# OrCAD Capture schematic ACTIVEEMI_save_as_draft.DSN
size Custom
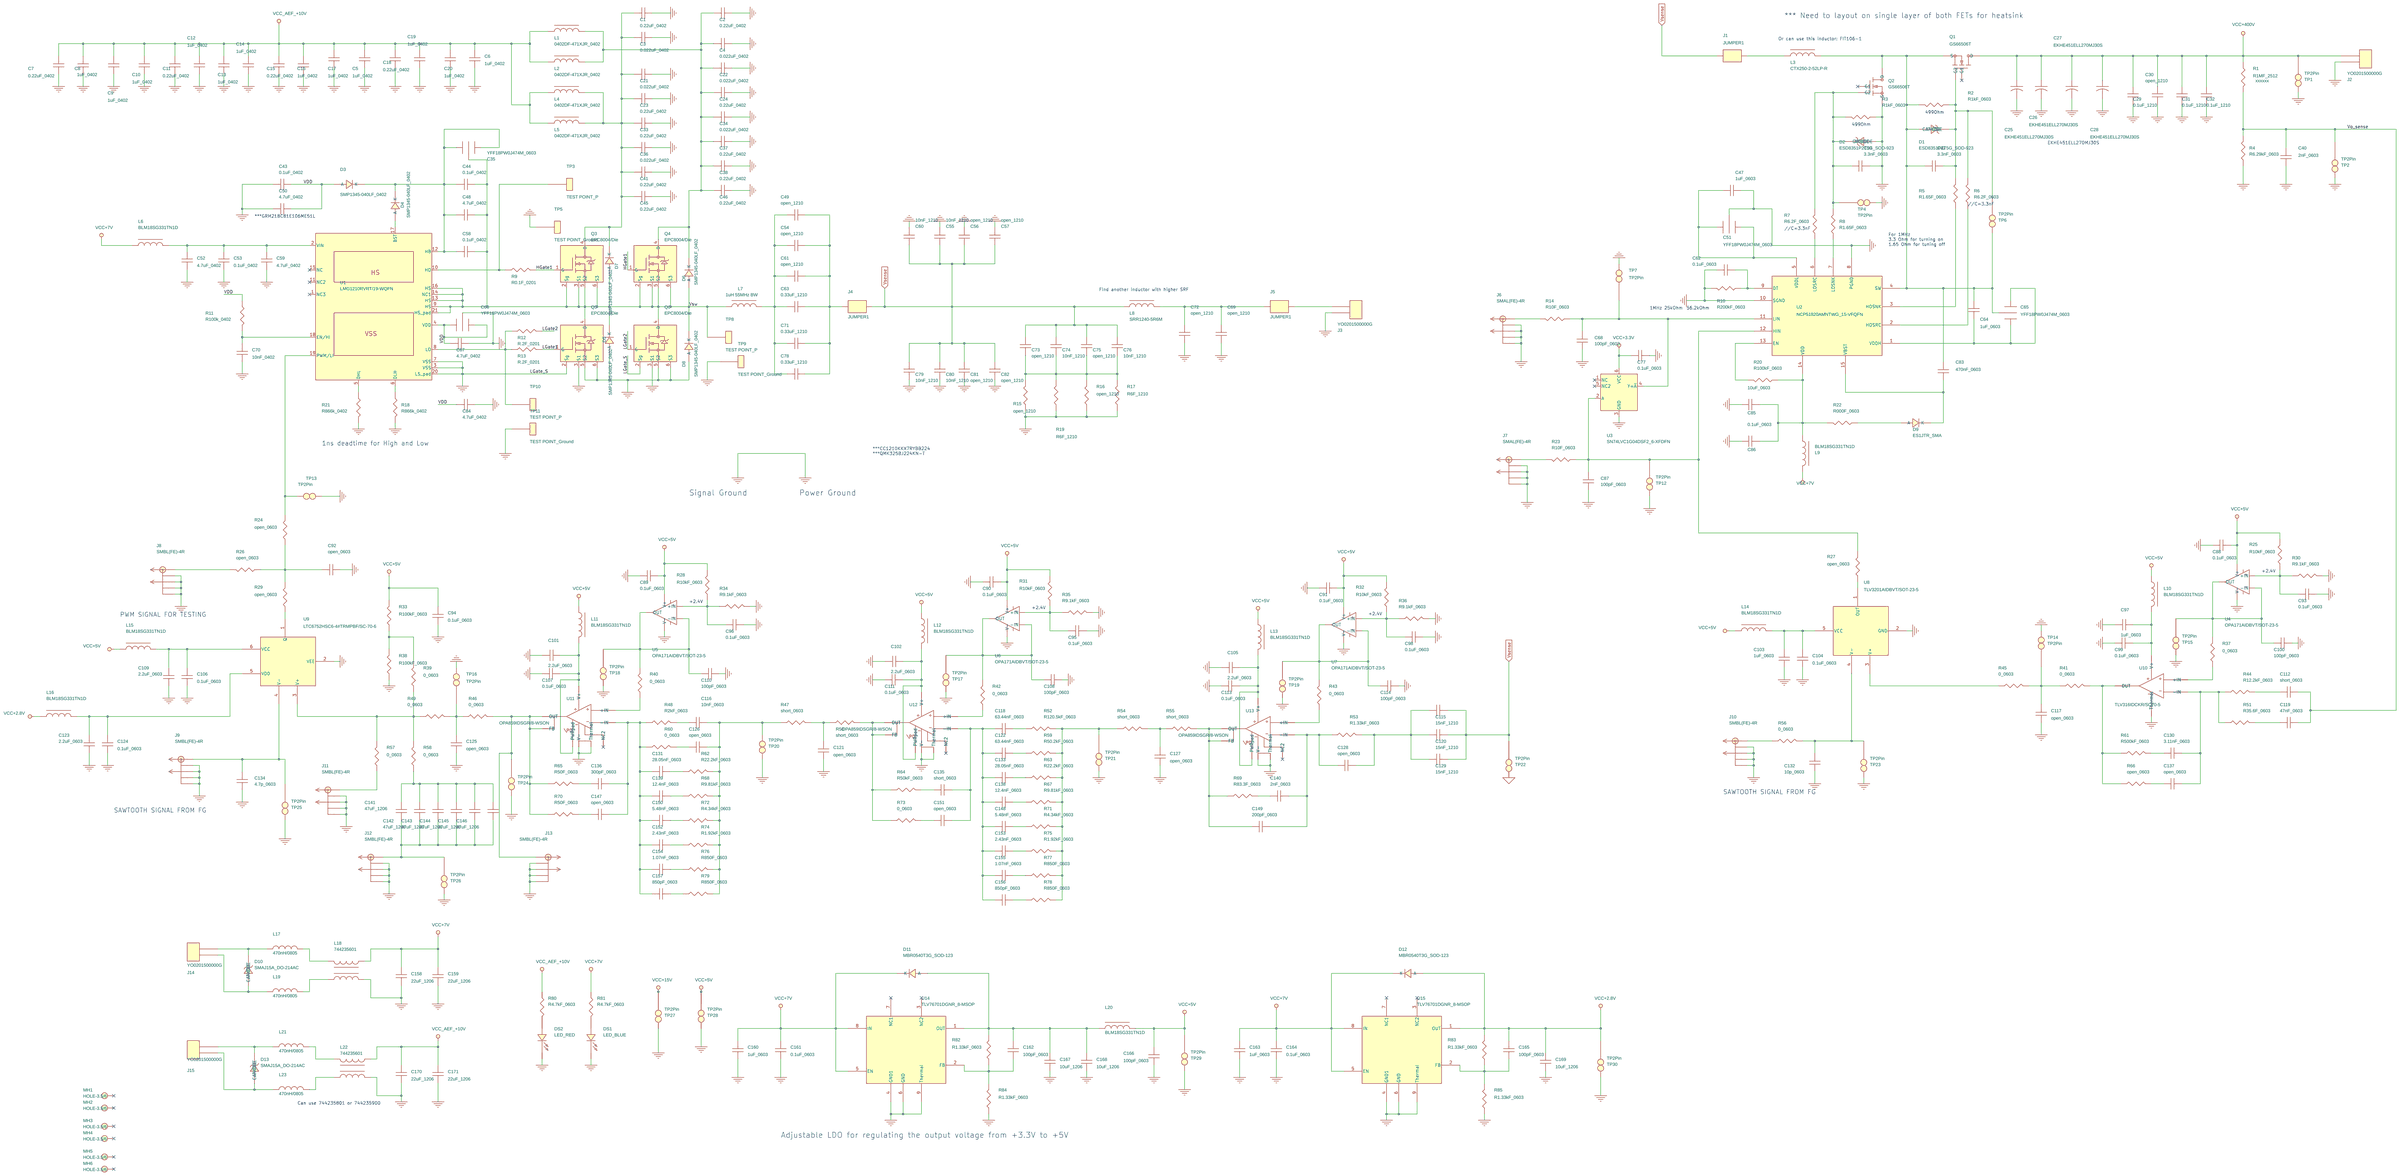
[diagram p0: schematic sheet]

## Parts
C1  0.22uF_0402  [C_0402_SMALL]
C2  0.22uF_0402  [C_0402_SMALL]
C3  0.022uF_0402  [C_0402_SMALL]
C4  0.022uF_0402  [C_0402_SMALL]
C5  1uF_0402  [C_0402_SMALL]
C6  1uF_0402  [C_0402_SMALL]
C7  0.22uF_0402  [C_0402_SMALL]
C8  1uF_0402  [C_0402_SMALL]
C9  1uF_0402  [C_0402_SMALL]
C10  1uF_0402  [C_0402_SMALL]
C11  0.22uF_0402  [C_0402_SMALL]
C12  1uF_0402  [C_0402_SMALL]
C13  1uF_0402  [C_0402_SMALL]
C14  1uF_0402  [C_0402_SMALL]
C15  0.22uF_0402  [C_0402_SMALL]
C16  1uF_0402  [C_0402_SMALL]
C17  1uF_0402  [C_0402_SMALL]
C18  0.22uF_0402  [C_0402_SMALL]
C19  1uF_0402  [C_0402_SMALL]
C20  1uF_0402  [C_0402_SMALL]
C21  0.022uF_0402  [C_0402_SMALL]
C22  0.022uF_0402  [C_0402_SMALL]
C23  0.22uF_0402  [C_0402_SMALL]
C24  0.22uF_0402  [C_0402_SMALL]
C25  EKHE451ELL270MJ30S  [450LXW100MEFR16X35]
C26  EKHE451ELL270MJ30S  [450LXW100MEFR16X35]
C27  EKHE451ELL270MJ30S  [450LXW100MEFR16X35]
C28  EKHE451ELL270MJ30S  [450LXW100MEFR16X35]
C29  0.1uF_1210  [22UF_1210]
C30  open_1210  [22UF_1210]
C31  0.1uF_1210  [22UF_1210]
C32  0.1uF_1210  [22UF_1210]
C33  0.22uF_0402  [C_0402_SMALL]
C34  0.022uF_0402  [C_0402_SMALL]
C35  YFF18PW0J474M_0603  [FEEDTHRU_0603]
C36  0.022uF_0402  [C_0402_SMALL]
C37  0.22uF_0402  [C_0402_SMALL]
C38  0.22uF_0402  [C_0402_SMALL]
C39  3.3nF_0603  [C1608]
C40  2nF_0603  [C1608]
C41  0.22uF_0402  [C_0402_SMALL]
C42  3.3nF_0603  [C1608]
C43  0.1uF_0402  [C_0402_SMALL]
C44  0.1uF_0402  [C_0402_SMALL]
C45  0.22uF_0402  [C_0402_SMALL]
C46  0.22uF_0402  [C_0402_SMALL]
C47  1uF_0603  [C1608]
C48  4.7uF_0402  [C_0402_SMALL]
C49  open_1210  [22UF_1210]
C50  4.7uF_0402  [C_0402_SMALL]
C51  YFF18PW0J474M_0603  [FEEDTHRU_0603]
C52  4.7uF_0402  [C_0402_SMALL]
C53  0.1uF_0402  [C_0402_SMALL]
C54  open_1210  [22UF_1210]
C55  10nF_1210  [22UF_1210]
C56  open_1210  [22UF_1210]
C57  open_1210  [22UF_1210]
C58  0.1uF_0402  [C_0402_SMALL]
C59  4.7uF_0402  [C_0402_SMALL]
C60  10nF_1210  [22UF_1210]
C61  open_1210  [22UF_1210]
C62  0.1uF_0603  [C1608]
C63  0.33uF_1210  [22UF_1210]
C64  1uF_0603  [C1608]
C65  YFF18PW0J474M_0603  [FEEDTHRU_0603]
C66  YFF18PW0J474M_0603  [FEEDTHRU_0603]
C67  4.7uF_0402  [C_0402_SMALL]
C68  100pF_0603  [C1608]
C69  open_1210  [22UF_1210]
C70  10nF_0402  [C_0402_SMALL]
C71  0.33uF_1210  [22UF_1210]
C72  open_1210  [22UF_1210]
C73  open_1210  [22UF_1210]
C74  10nF_1210  [22UF_1210]
C75  open_1210  [22UF_1210]
C76  10nF_1210  [22UF_1210]
C77  0.1uF_0603  [C1608]
C78  0.33uF_1210  [22UF_1210]
C79  10nF_1210  [22UF_1210]
C80  10nF_1210  [22UF_1210]
C81  open_1210  [22UF_1210]
C82  open_1210  [22UF_1210]
C83  470nF_0603  [C1608]
C84  4.7uF_0402  [C_0402_SMALL]
C85  10uF_0603  [C1608]
C86  0.1uF_0603  [C1608]
C87  100pF_0603  [C1608]
C88  0.1uF_0603  [C1608]
C89  0.1uF_0603  [C1608]
C90  0.1uF_0603  [C1608]
C91  0.1uF_0603  [C1608]
C92  open_0603  [C1608]
C93  0.1uF_0603  [C1608]
C94  0.1uF_0603  [C1608]
C95  0.1uF_0603  [C1608]
C96  0.1uF_0603  [C1608]
C97  1uF_0603  [C1608]
C98  0.1uF_0603  [C1608]
C99  0.1uF_0603  [C1608]
C100  100pF_0603  [C1608]
C101  2.2uF_0603  [C1608]
C102  2.2uF_0603  [C1608]
C103  1uF_0603  [C1608]
C104  0.1uF_0603  [C1608]
C105  2.2uF_0603  [C1608]
C106  0.1uF_0603  [C1608]
C107  0.1uF_0603  [C1608]
C108  100pF_0603  [C1608]
C109  2.2uF_0603  [C1608]
C110  100pF_0603  [C1608]
C111  0.1uF_0603  [C1608]
C112  short_0603  [C1608]
C113  0.1uF_0603  [C1608]
C114  100pF_0603  [C1608]
C115  15nF_1210  [22UF_1210]
C116  10nF_0603  [C1608]
C117  open_0603  [C1608]
C118  63.44nF_0603  [C1608]
C119  47nF_0603  [C1608]
C120  15nF_1210  [22UF_1210]
C121  open_0603  [C1608]
C122  63.44nF_0603  [C1608]
C123  2.2uF_0603  [C1608]
C124  0.1uF_0603  [C1608]
C125  open_0603  [C1608]
C126  open_0603  [C1608]
C127  open_0603  [C1608]
C128  open_0603  [C1608]
C129  15nF_1210  [22UF_1210]
C130  3.11nF_0603  [C1608]
C131  28.05nF_0603  [C1608]
C132  10p_0603  [C1608]
C133  28.05nF_0603  [C1608]
C134  4.7p_0603  [C1608]
C135  short_0603  [C1608]
C136  300pF_0603  [C1608]
C137  open_0603  [C1608]
C138  12.4nF_0603  [C1608]
C139  12.4nF_0603  [C1608]
C140  2nF_0603  [C1608]
C141  47uF_1206  [OPEN_1206]
C142  47uF_1206  [OPEN_1206]
C143  47uF_1206  [OPEN_1206]
C144  47uF_1206  [OPEN_1206]
C145  47uF_1206  [OPEN_1206]
C146  47uF_1206  [OPEN_1206]
C147  open_0603  [C1608]
C148  5.48nF_0603  [C1608]
C149  200pF_0603  [C1608]
C150  5.48nF_0603  [C1608]
C151  open_0603  [C1608]
C152  2.43nF_0603  [C1608]
C153  2.43nF_0603  [C1608]
C154  1.07nF_0603  [C1608]
C155  1.07nF_0603  [C1608]
C156  850pF_0603  [C1608]
C157  850pF_0603  [C1608]
C158  22uF_1206  [OPEN_1206]
C159  22uF_1206  [OPEN_1206]
C160  1uF_0603  [C1608]
C161  0.1uF_0603  [C1608]
C162  100pF_0603  [C1608]
C163  1uF_0603  [C1608]
C164  0.1uF_0603  [C1608]
C165  100pF_0603  [C1608]
C166  100pF_0603  [C1608]
C167  10uF_1206  [OPEN_1206]
C168  10uF_1206  [OPEN_1206]
C169  10uF_1206  [OPEN_1206]
C170  22uF_1206  [OPEN_1206]
C171  22uF_1206  [OPEN_1206]
D1  ESD8351P2T5G_SOD-923  [ESD8351P2T5G]
D2  ESD8351P2T5G_SOD-923  [ESD8351P2T5G]
D3  SMP1345-040LF_0402  [SMP1345-040LF]
D4  SMP1345-040LF_0402  [SMP1345-040LF]
D5  SMP1345-040LF_0402  [SMP1345-040LF]
D6  SMP1345-040LF_0402  [SMP1345-040LF]
D7  SMP1345-040LF_0402  [SMP1345-040LF]
D8  SMP1345-040LF_0402  [SMP1345-040LF]
D9  ES1JTR_SMA  [SMAJ6.0CA_DO-214AC]
D10  SMAJ15A_DO-214AC  [SMAJ6.0CA_DO-214AC]
D11  MBR0540T3G_SOD-123  [MBR0540T3G_SOD-123]
D12  MBR0540T3G_SOD-123  [MBR0540T3G_SOD-123]
D13  SMAJ15A_DO-214AC  [SMAJ6.0CA_DO-214AC]
DS1  LED_BLUE  [598-8170-107F]
DS2  LED_RED  [598-8170-107F]
J1  JUMPER1  [JUMPER3]
J2  YO0201500000G  [YO0201500000G]
J3  YO0201500000G  [YO0201500000G]
J4  JUMPER1  [JUMPER3]
J5  JUMPER1  [JUMPER3]
J6  SMAL(FE)-4R  [SMBL(FE)-4R]
J7  SMAL(FE)-4R  [SMBL(FE)-4R]
J8  SMBL(FE)-4R  [SMBL(FE)-4R]
J9  SMBL(FE)-4R  [SMBL(FE)-4R]
J10  SMBL(FE)-4R  [SMBL(FE)-4R]
J11  SMBL(FE)-4R  [SMBL(FE)-4R]
J12  SMBL(FE)-4R  [SMBL(FE)-4R]
J13  SMBL(FE)-4R  [SMBL(FE)-4R]
J14  YO0201500000G  [YO0201500000G]
J15  YO0201500000G  [YO0201500000G]
L1  0402DF-471XJR_0402  [L_0402_SMALL]
L2  0402DF-471XJR_0402  [L_0402_SMALL]
L3  CTX250-2-52LP-R  [CTX250-2-52LP-R]
L4  0402DF-471XJR_0402  [L_0402_SMALL]
L5  0402DF-471XJR_0402  [L_0402_SMALL]
L6  BLM18SG331TN1D  [L1608]
L7  1uH 55MHz BW  [SRR5028-6R2Y]
L8  SRR1240-5R6M  [SRR1240-5R6M]
L9  BLM18SG331TN1D  [L1608]
L10  BLM18SG331TN1D  [L1608]
L11  BLM18SG331TN1D  [L1608]
L12  BLM18SG331TN1D  [L1608]
L13  BLM18SG331TN1D  [L1608]
L14  BLM18SG331TN1D  [L1608]
L15  BLM18SG331TN1D  [L1608]
L16  BLM18SG331TN1D  [L1608]
L17  470nH/0805
L18  744235601  [L1608]
L19  470nH/0805
L20  BLM18SG331TN1D  [L1608]
L21  470nH/0805
L22  744235601  [L1608]
L23  470nH/0805
MH1  HOLE-3.5/6  [HOLE-3.2/6]
MH2  HOLE-3.5/6  [HOLE-3.2/6]
MH3  HOLE-3.5/6  [HOLE-3.2/6]
MH4  HOLE-3.5/6  [HOLE-3.2/6]
MH5  HOLE-3.5/6  [HOLE-3.2/6]
MH6  HOLE-3.5/6  [HOLE-3.2/6]
Q1  GS66506T  [GS66506T]
Q2  GS66506T  [GS66506T]
Q3  EPC8004/Die  [EPC8004/DIE]
Q4  EPC8004/Die  [EPC8004/DIE]
Q5  EPC8004/Die  [EPC8004/DIE]
Q6  EPC8004/Die  [EPC8004/DIE]
R1  R1MF_2512  [R_2512]
R2  R1kF_0603  [R_1608]
R3  R1kF_0603  [R_1608]
R4  R6.29kF_0603  [R_1608]
R5  R1.65F_0603  [R_1608]
R6  R6.2F_0603  [R_1608]
R7  R6.2F_0603  [R_1608]
R8  R1.65F_0603  [R_1608]
R9  R0.1F_0201  [R_0201_SHORT]
R10  R200kF_0603  [R_1608]
R11  R100k_0402  [R_0402_SHORT]
R12  R.2F_0201  [R_0201_SHORT]
R13  R.2F_0201  [R_0201_SHORT]
R14  R10F_0603  [R_1608]
R15  open_1210  [1R0_1210]
R16  open_1210  [1R0_1210]
R17  R6F_1210  [1R0_1210]
R18  R866k_0402  [R_0402_SHORT]
R19  R6F_1210  [1R0_1210]
R20  R100kF_0603  [R_1608]
R21  R866k_0402  [R_0402_SHORT]
R22  R000F_0603  [R_1608]
R23  R10F_0603  [R_1608]
R24  open_0603  [R_1608]
R25  R10kF_0603  [R_1608]
R26  open_0603  [R_1608]
R27  open_0603  [R_1608]
R28  R10kF_0603  [R_1608]
R29  open_0603  [R_1608]
R30  R9.1kF_0603  [R_1608]
R31  R10kF_0603  [R_1608]
R32  R10kF_0603  [R_1608]
R33  R100kF_0603  [R_1608]
R34  R9.1kF_0603  [R_1608]
R35  R9.1kF_0603  [R_1608]
R36  R9.1kF_0603  [R_1608]
R37  0_0603  [R_1608]
R38  R100kF_0603  [R_1608]
R39  0_0603  [R_1608]
R40  0_0603  [R_1608]
R41  0_0603  [R_1608]
R42  0_0603  [R_1608]
R43  0_0603  [R_1608]
R44  R12.2kF_0603  [R_1608]
R45  0_0603  [R_1608]
R46  0_0603  [R_1608]
R47  short_0603  [R_1608]
R48  R2kF_0603  [R_1608]
R49  0_0603  [R_1608]
R50  short_0603  [R_1608]
R51  R35.6F_0603  [R_1608]
R52  R120.5kF_0603  [R_1608]
R53  R1.33kF_0603  [R_1608]
R54  short_0603  [R_1608]
R55  short_0603  [R_1608]
R56  0_0603  [R_1608]
R57  0_0603  [R_1608]
R58  0_0603  [R_1608]
R59  R50.2kF_0603  [R_1608]
R60  0_0603  [R_1608]
R61  R500kF_0603  [R_1608]
R62  R22.2kF_0603  [R_1608]
R63  R22.2kF_0603  [R_1608]
R64  R50kF_0603  [R_1608]
R65  R50F_0603  [R_1608]
R66  open_0603  [R_1608]
R67  R9.81kF_0603  [R_1608]
R68  R9.81kF_0603  [R_1608]
R69  R83.3F_0603  [R_1608]
R70  R50F_0603  [R_1608]
R71  R4.34kF_0603  [R_1608]
R72  R4.34kF_0603  [R_1608]
R73  0_0603  [R_1608]
R74  R1.92kF_0603  [R_1608]
R75  R1.92kF_0603  [R_1608]
R76  R850F_0603  [R_1608]
R77  R850F_0603  [R_1608]
R78  R850F_0603  [R_1608]
R79  R850F_0603  [R_1608]
R80  R4.7kF_0603  [R_1608]
R81  R4.7kF_0603  [R_1608]
R82  R1.33kF_0603  [R_1608]
R83  R1.33kF_0603  [R_1608]
R84  R1.33kF_0603  [R_1608]
R85  R1.33kF_0603  [R_1608]
TP1  TP2Pin  [TP2PIN]
TP2  TP2Pin  [TP2PIN]
TP3  TEST POINT_P  [TP1PIN_POS]
TP4  TP2Pin  [TP2PIN]
TP5  TEST POINT_Ground  [TP1PIN_NEG]
TP6  TP2Pin  [TP2PIN]
TP7  TP2Pin  [TP2PIN]
TP8  TEST POINT_P  [TP1PIN_POS]
TP9  TEST POINT_Ground  [TP1PIN_POS]
TP10  TEST POINT_P  [TP1PIN_POS]
TP11  TEST POINT_Ground  [TP1PIN_NEG]
TP12  TP2Pin  [TP2PIN]
TP13  TP2Pin  [TP2PIN]
TP14  TP2Pin  [TP2PIN]
TP15  TP2Pin  [TP2PIN]
TP16  TP2Pin  [TP2PIN]
TP17  TP2Pin  [TP2PIN]
TP18  TP2Pin  [TP2PIN]
TP19  TP2Pin  [TP2PIN]
TP20  TP2Pin  [TP2PIN]
TP21  TP2Pin  [TP2PIN]
TP22  TP2Pin  [TP2PIN]
TP23  TP2Pin  [TP2PIN]
TP24  TP2Pin  [TP2PIN]
TP25  TP2Pin  [TP2PIN]
TP26  TP2Pin  [TP2PIN]
TP27  TP2Pin  [TP2PIN]
TP28  TP2Pin  [TP2PIN]
TP29  TP2Pin  [TP2PIN]
TP30  TP2Pin  [TP2PIN]
U1  LMG1210RVRT/19-WQFN  [LMG1210RVRT]
U2  NCP51820AMNTWG_15-VFQFN  [NCP51810AMNTWG]
U3  SN74LVC1G04DSF2_6-XFDFN  [SN74LVC1G04DSF2]
U4  OPA171AIDBVT/SOT-23-5  [SN74LVC1G14DBVR_SOT-23-5]
U5  OPA171AIDBVT/SOT-23-5  [SN74LVC1G14DBVR_SOT-23-5]
U6  OPA171AIDBVT/SOT-23-5  [SN74LVC1G14DBVR_SOT-23-5]
U7  OPA171AIDBVT/SOT-23-5  [SN74LVC1G14DBVR_SOT-23-5]
U8  TLV3201AIDBVT/SOT-23-5  [SOT-363]
U9  LTC6752HSC6-4#TRMPBF/SC-70-6  [SOT-363]
U10  TLV316IDCKR/SC70-5  [DJN_IC_8-SOIC]
U11  OPA859IDSGR/8-WSON  [DJN_IC_8-SOIC]
U12  OPA859IDSGR/8-WSON  [DJN_IC_8-SOIC]
U13  OPA859IDSGR/8-WSON  [DJN_IC_8-SOIC]
U14  TLV76701DGNR_8-MSOP  [SOT-363]
U15  TLV76701DGNR_8-MSOP  [SOT-363]

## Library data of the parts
C1-C24 C29-C34 C36-C50 C52-C64 C67-C140 C147-C157 C160-C166 = CAP_NP_1
C25-C28 = CAP_0
C35 C51 C65 C66 = CAP_NP_0
C141-C146 = CAP_NP_1: PART NO: 40000677
C158 C159 C167-C171 = CAP_NP_1: PART NO: 151273
D1 D2 = DIODE_ZENER_0: PART NO: 40002129
D3-D8 = DIODE_1
D9 D11 D12 = DIODE_5: PART NO: 40001919
D10 D13 = DIODE_ZENER_0
DS1 DS2 = LED_0
J1 J4 J5 = CON2_1
J2 J3 J14 J15 = CON2
J6-J13 = 142-0701-506_0
L1-L5 L7 L8 = INDUCTOR_4
L6 L9-L16 L20 = CHOKE_1_v2
L17 L19 L21 L23 = INDUCTOR
L18 L22 = CHOKE_2
MH1-MH6 = T_POINT_R
Q1 Q2 = IRFZ24N_TO_5: PART NO: 1063683; PATH NO: 1063683
Q3-Q6 = IRFZ24N_TO_2: PATH NO: 1063683
R1 = RESISTOR_0: PART NO: xxxxxx
R2-R14 R18 R20-R79 R82-R85 = R_0
R15-R17 R19 = RESISTOR_0: PART NO: 40000659
R80 R81 = RESISTOR
TP1 TP2 TP4 TP6 TP7 TP12-TP30 = T_POINT_R_1
TP3 TP5 TP8-TP11 = TEST_POINT
U1 = CON20A_5
U2 = CON8A_4_v2
U3 = CON6A_0
U4-U7 = OPA131_SO_0
U8 = CON8A_7
U9 = CON8A_8
U10 = OPA658_SOT_2
U11-U13 = OPA658_SOT_1
U14 U15 = CON8A_6

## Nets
GND_POWER: C1.1 C2.1 C3.1 C4.1 C5.1 C6.1 C7.1 C8.1 C9.1 C10.1 C11.1 C12.1 C13.1 C14.1 C15.1 C16.1 C17.1 C18.1 C19.1 C20.1 C21.1 C22.1 C23.1 C24.1 C25.2 C26.2 C27.2 C28.2 C29.2 C30.2 C31.2 C32.2 C33.1 C34.1 C36.1 C37.1 C38.1 C39.2 C40.1 C41.1 C43.2 C45.1 C46.1 C47.2 C50.2 C51.3 C52.2 C53.2 C55.2 C56.2 C57.2 C59.2 C60.2 C62.1 C66.3 C67.1 C68.1 C69.2 C70.1 C72.2 C77.2 C79.2 C80.2 C81.2 C82.2 C84.1 C85.1 C86.1 C87.1 C88.1 C89.1 C90.1 C91.1 C92.1 C93.2 C94.1 C95.2 C96.2 C97.2 C98.2 C99.1 C100.2 C101.2 C102.2 C103.1 C104.1 C105.2 C106.1 C107.1 C108.2 C109.1 C110.2 C111.1 C113.1 C114.2 C117.1 C121.1 C123.1 C124.1 C125.1 C127.1 C132.1 C134.1 C158.2 C159.2 C160.1 C161.1 C163.1 C164.1 C166.1 C167.2 C168.2 C169.2 C170.2 C171.2 D2.1(ANODE) D7.1(A) D8.1(A) DS1.1(CATHODE) DS2.1(CATHODE) J2.1 J3.1 J6.2 J6.3 J6.4 J6.5 J7.2 J7.3 J7.4 J7.5 J8.2 J8.3 J8.4 J8.5 J9.2 J9.3 J9.4 J9.5 J10.2 J10.3 J10.4 J10.5 J11.2 J11.3 J11.4 J11.5 J12.2 J12.3 J12.4 J12.5 J13.2 J13.3 J13.4 J13.5 L18.3 L22.3 Q2.3(S) Q5.2(Sg) Q5.3(S1) Q5.5(S2) Q5.6(S3) Q6.2(Sg) Q6.3(S1) Q6.5(S2) Q6.6(S3) R3.2 R4.2 R10.1 R15.1 R16.1 R17.1 R18.1 R19.1 R21.1 R30.1 R34.1 R35.1 R36.1 R38.2 R84.2 R85.2 TP1.2(GND) TP2.2(GND) TP4.2(GND) TP5.1 TP7.2(GND) TP9.1 TP11.1 TP12.2(GND) TP13.2(GND) TP14.2(GND) TP15.2(GND) TP16.2(GND) TP17.2(GND) TP18.2(GND) TP19.2(GND) TP20.2(GND) TP21.2(GND) TP22.2(GND) TP23.2(GND) TP24.2(GND) TP25.2(GND) TP26.2(GND) TP27.2(GND) TP28.2(GND) TP29.2(GND) TP30.2(GND) U1.3(VSS) U1.7(VSS) U1.20(LS_pad) U2.8(PGND) U2.10(SGND) U3.3(GND) U4.2(V-) U5.2(V-) U6.2(V-) U7.2(V-) U8.2(GND) U9.2(VEE) U10.2(Thermal) U11.5(V-) U11.9(Thermal) U12.5(V-) U12.9(Thermal) U13.5(V-) U13.9(Thermal) U14.4(GND1) U14.6(GND) U14.9(Thermal) U15.4(GND1) U15.6(GND) U15.9(Thermal)
Vcc+2.8V: C165.2 C169.1 D12.1(A) L16.1 R83.1 TP30.1(TP) U15.1(OUT)
Vcc+3.3V: C77.1 U3.6(VCC)
Vcc+5V: C88.2 C89.2 C90.2 C91.2 C94.2 C166.2 L10.1 L11.1 L12.1 L13.1 L14.1 L15.1 L20.2 R25.1 R28.1 R31.1 R32.1 R33.1 TP28.1(TP) TP29.1(TP) U4.5(V+) U5.5(V+) U6.5(V+) U7.5(V+)
Vcc+7V: C158.1 C159.1 C160.2 C161.2 C163.2 C164.2 D11.2(K) D12.2(K) L6.1 L9.1 L18.4 R81.1 U14.5(EN) U14.8(IN) U15.5(EN) U15.8(IN)
Vcc+15V: TP27.1(TP)
Vcc+400V: C25.1 C26.1 C27.1 C28.1 C29.1 C30.1 C31.1 C32.1 J2.2 Q1.1(D) R1.1 TP1.1(TP)
Vcc_AEF_+10V: C5.2 C6.2 C7.2 C8.2 C9.2 C10.2 C11.2 C12.2 C13.2 C14.2 C15.2 C16.2 C17.2 C18.2 C19.2 C20.2 C170.1 C171.1 L1.1 L2.1 L4.1 L5.1 L22.4 R80.1
VDD: C43.1 C50.1 C66.1 C66.2 C67.2 C84.2 D3.1(A) R11.2 U1.4(VDD)
HGate1: Q3.1(G) Q4.1(G) R9.1
LGate1: Q5.1(G) R13.1
LGate2: Q6.1(G) R12.1
Vo_sense: C40.2 C112.2 C119.2 R1.2 R4.1 TP2.1(TP)
Vsense: C55.1 C56.1 C57.1 C60.1 C73.1 C74.1 C75.1 C76.1 C79.1 C80.1 C81.1 C82.1 C115.2 C120.2 C129.2 J1.1 J4.2 L8.1 TP22.1(TP)
Vsw: C35.3 C44.1 C48.1 C58.1 D5.1(A) D6.1(A) D7.2(K) D8.2(K) L7.1 Q3.2(Sg) Q3.3(S1) Q3.5(S2) Q3.6(S3) Q4.2(Sg) Q4.3(S1) Q4.5(S2) Q4.6(S3) Q5.4(D) Q6.4(D) TP8.1 U1.9(HS) U1.13(HS) U1.14(NC1) U1.16(HS) U1.21(HS_pad)
N14344006: J8.1 R26.1
N14345447: C1.2 C3.2 C21.2 C23.2 C33.2 C36.2 C41.2 C45.2 D5.2(K) L4.2 L5.2 Q3.4(D)
N14345453: C2.2 C4.2 C22.2 C24.2 C34.2 C37.2 C38.2 C46.2 D6.2(K) L1.2 L2.2 Q4.4(D)
N14345780: C49.2 C54.2 C61.2 C63.2 C71.2 C78.2 L7.2
N14345880: C49.1 C54.1 C61.1 C63.1 C71.1 C78.1 J4.1
N14346983: C73.2 C74.2 C75.2 C76.2 R15.2 R16.2 R17.2 R19.2
N14347554: C69.1 C72.1 J5.1 L8.2
N14354653: C128.1 C140.2 C149.2 R53.2 U13.3(-IN)
N14354665: C115.1 C120.1 C128.2 C129.1 R53.1
N14355323: C140.1 R69.1
N14355343: C149.1 R55.1 R69.2 U13.1(FB) U13.6(OUT)
N14355725: C105.1 C113.2 L13.2 U13.7(V+) U13.8(PWRpad)
N14356817: C114.1 R43.1 TP19.1(TP) U7.1(OUT) U7.4(-IN)
N14357408: C98.1 R32.2 R36.2 U7.3(+IN)
N14359999: C95.1 R31.2 R35.2 U6.3(+IN)
N14360059: C108.1 R42.1 TP17.1(TP) U6.1(OUT) U6.4(-IN)
N14360113: C102.1 C111.2 L12.2 U12.7(V+) U12.8(PWRpad)
N14360199: R42.2 U12.4(+IN)
N14360273: R50.1 R64.2 R73.2 U12.1(FB) U12.6(OUT)
N14360317: C118.1 C122.1 C133.1 C135.2 C138.1 C148.1 C151.2 C153.1 C155.1 C156.1 U12.3(-IN)
N14360349: R52.1 R54.2 R59.1 R63.1 R67.1 R71.1 R75.1 R77.1 R78.1 TP21.1(TP)
N14360383: C122.2 R59.2
N14360443: C135.1 R64.1
N14361433: C133.2 R63.2
N14361580: C138.2 R67.2
N14361733: C148.2 R71.2
N14361896: C153.2 R75.2
N14362063: C155.2 R77.2
N14363997: C96.1 R28.2 R34.2 U5.3(+IN)
N14364057: C110.1 R40.1 TP18.1(TP) U5.1(OUT) U5.4(-IN)
N14364111: C101.1 C107.2 L11.2 U11.7(V+) U11.8(PWRpad)
N14364215: R40.2 U11.4(+IN)
N14364289: C125.2 R46.2 R49.1 TP16.1(TP)
N14364293: J13.1 R46.1 R65.2 R70.2 TP24.1(TP) U11.1(FB) U11.6(OUT)
N14364337: C131.1 C136.2 C139.1 C147.2 C150.1 C152.1 C154.1 C157.1 R48.2 R60.2 U11.3(-IN)
N14364357: C116.1 R48.1
N14364499: C136.1 R65.1
N14364777: C116.2 C126.2 R47.2 R62.1 R68.1 R72.1 R74.1 R76.1 R79.1 TP20.1(TP)
N14365632: R39.2 R49.2 R57.1 R58.1 U9.3(V+)
N14367350: C134.2 J9.1 TP25.1(TP) U9.4(V-)
N14371364: C106.2 C109.2 L15.2 U9.6(VCC)
N14372288: R29.2 U9.1(Q)
N14372493: C92.2 R24.2 R26.2 R29.1
N14376814: R21.2 U1.5(DHL)
N14376818: R18.2 U1.6(DLH)
N14377829: R24.1 TP13.1(TP) U1.19(PWM/LI)
N14377848: R12.2 R13.2 TP10.1 U1.8(LO)
N14377884: R9.2 TP3.1 U1.10(HO)
N14378663: C35.1 C35.2 C44.2 C48.2 C58.2 D3.2(K) D4.2(K) U1.12(HB)
N14384475: C52.1 C53.1 C59.1 L6.2 U1.2(VIN)
N14385796: C70.2 R11.1 U1.18(EN/HI)
N14555005: D4.1(A) U1.17(BST)
N14663437: J11.1 R57.2
N14670381: C141.2 C142.2 C143.2 C144.2 C145.2 C146.2 J12.1 TP26.1(TP)
N14671227: R33.2 R38.1 R39.1
N14672368: C141.1 C142.1 C143.1 C144.1 C145.1 C146.1 R58.2
N14984314: J1.2 L3.1
N14984318: C42.1 C64.2 C65.3 C83.2 D1.1(ANODE) L3.2 Q1.3(S) Q2.1(D) R2.1 TP6.2(GND) U2.4(SW)
N14984498: C42.2 D1.2(CATHODE) Q1.4(G2) R2.2 R5.1 R6.1 TP6.1(TP)
N14984596: C39.1 D2.2(CATHODE) Q2.4(G2) R3.1 R7.1 R8.1 TP4.1(TP)
N14985160: C47.1 C51.1 C51.2 U2.5(VDDL)
N14985270: R5.2 U2.3(HOSNK)
N14985274: R6.2 U2.2(HOSRC)
N14985492: R7.2 U2.6(LOSRC)
N14985496: R8.2 U2.7(LOSNK)
N14985592: C62.2 R10.2 U2.9(DT)
N14985712: C64.1 C65.1 C65.2 U2.1(VDDH)
N14985832: C68.2 R14.2 TP7.1(TP) U2.11(LIN) U3.4(Y=~{A})
N14985848: C87.2 R23.2 R27.1 TP12.1(TP) U2.12(HIN) U3.2(A)
N14985890: R20.1 U2.13(EN)
N14986004: C85.2 C86.2 L9.2 R20.2 R22.1 U2.14(VDD)
N14986008: C83.1 D9.2(K) U2.15(VBST)
N14986190: D9.1(A) R22.2
N14986300: J7.1 R23.1
N15044775: D10.2(CATHODE) J14.2 L17.1
N15044799: D10.1(ANODE) J14.1 L19.1
N15044925: D13.2(CATHODE) J15.2 L21.1
N15044949: D13.1(ANODE) J15.1 L23.1
N15050534: R43.2 U13.4(+IN)
N15060765: C156.2 R78.2
N15060962: C118.2 R52.2
N15061047: C151.1 R73.1
N15061956: C127.2 R54.1 R55.2
N15062861: C126.1 R60.1
N15062981: C147.1 R70.1
N15067555: C121.2 R47.1 R50.2
N15072530: C131.2 R62.2
N15072586: C139.2 R68.2
N15072642: C150.2 R72.2
N15072698: C152.2 R74.2
N15072754: C154.2 R76.2
N15072806: C157.2 R79.2
N15082070: J3.2 J5.2
N15096202: L17.2 L18.2
N15096209: L18.1 L19.2
N15101746: L21.2 L22.2
N15101792: L22.1 L23.2
N15112885: C93.1 R25.2 R30.2 U4.3(+IN)
N15112945: C100.1 R37.1 TP15.1(TP) U4.1(OUT) U4.4(-IN)
N15112999: C97.1 C99.2 L10.2 U10.5(V+)
N15113221: R37.2 U10.1(+IN)
N15113263: R41.1 R61.2 R66.2 U10.4(OUT)
N15113315: C130.2 C137.2 R44.2 R51.2 U10.3(-IN)
N15113495: C130.1 R61.1
N15114127: C137.1 R66.1
N15114162: C112.1 R44.1
N15114229: C119.1 R51.1
N15116463: R45.2 U8.3(V+)
N15116475: C117.2 R41.2 R45.1 TP14.1(TP)
N15121576: J10.1 R56.2
N15121580: C132.2 R56.1 TP23.1(TP) U8.4(V-)
N15125471: J6.1 R14.1
N15127169: C103.2 C104.2 L14.2 U8.5(VCC)
N15146596: C162.2 C167.1 C168.1 D11.1(A) L20.1 R82.1 U14.1(OUT)
N15151268: C162.1 R82.2 R84.1 U14.2(FB)
N15167322: R27.2 U8.1(OUT)
N15175203: DS2.2(ANODE) R80.2
N15175204: DS1.2(ANODE) R81.2
N15177218: C123.2 C124.2 L16.2 U9.5(VDD)
N15178577: C165.1 R83.2 R85.1 U15.2(FB)

Not connected (* = marked no-connect by the designer): MH1 1(TP)*; MH2 1(TP)*; MH3 1(TP)*; MH4 1(TP)*; MH5 1(TP)*; MH6 1(TP)*; Q1 2(G1)*; Q2 2(G1)*; U1 1(NC3)* 11(NC2)* 15(NC)*; U3 1(NC)* 5(NC2)*; U11 2(NC2)*; U12 2(NC2)*; U13 2(NC2)*; U14 3(NC2)* 7(NC1)*; U15 3(NC2)* 7(NC1)*

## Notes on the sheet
- *** Need to layout on single layer of both FETs for heatsink
- Or can use this inductor: FIT106-1
- 499Ohm
- 499Ohm
- EKHE451ELL270MJ30S
- //C=3.3nF
- ***GRM21BC81E106ME51L
- //C=3.3nF
- For 1MHz
  3.3 Ohm for turning on
  1.65 Ohm for tuning off
- Find another inductor with higher SRF
- 1MHz 25kOhm
- 56.2kOhm
- 1ns deadtime for High and Low
- ***CC1210KKX7RYBB224
  ***QMK325BJ224KN-T
- Signal Ground
- Power Ground
- +2.4V
- +2.4V
- +2.4V
- PWM SIGNAL FOR TESTING
- +2.4V
- SAWTOOTH SIGNAL FROM FG
- SAWTOOTH SIGNAL FROM FG
- Can use 744235801 or 744235900
- Adjustable LDO for regulating the output voltage from +3.3V to +5V
